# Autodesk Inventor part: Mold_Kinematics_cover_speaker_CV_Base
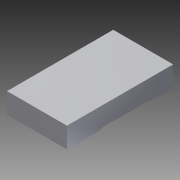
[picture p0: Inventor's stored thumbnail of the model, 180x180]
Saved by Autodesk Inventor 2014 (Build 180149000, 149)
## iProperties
Created: 2009-12
Part Number: Mold_Kinematics_cover_speaker_CV_Base
Document SubType Name: Modeling
Designer: gaom
Density: 1 g/cm^3
Material: Generic
Appearance: Default
Author: gaom
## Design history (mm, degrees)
node "Mold_Kinematics_cover_speaker_MP"
feature "Solid4::Mold_Kinematics_cover_speaker_MP"
tag "TaggingFeature1"
body "Solid1"
